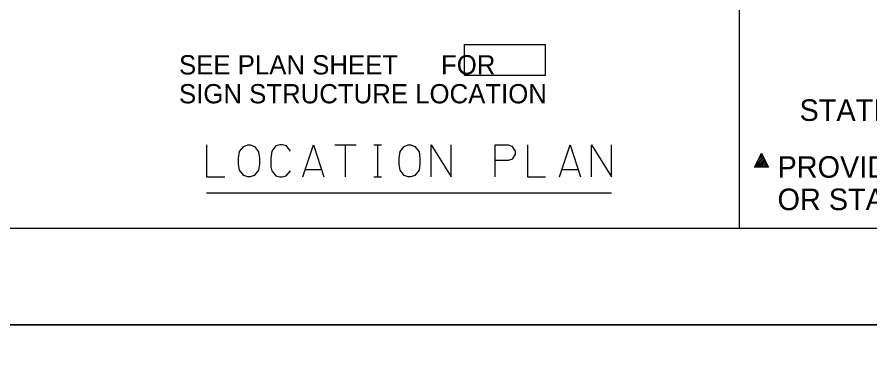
# Model space of a CAD drawing. Extents: x 3831399 to 3833095, y 499014 to 500202.
# Drawn here: x 3832621.3 to 3832754.1, y 499600.5 to 499655.9 of the extents above; entities that cross this region are included whole.
import ezdxf

# ---------------------------------------------------------------- set-up
doc = ezdxf.new("R2010")
doc.units = 0
for name, color, linetype in [('2', 7, 'Continuous'), ('DIM TXT', 7, 'Continuous'), ('Level 10', 7, 'Continuous'), ('Level 2', 7, 'Continuous'), ('PLT-BNDY', 7, 'Continuous')]:
    doc.layers.add(name, color=color, linetype=linetype)

msp = doc.modelspace()

# ---------------------------------------------------------------- linework, layer by layer
at = {"layer": '2'}
msp.add_line((3833066.16, 499623.03), (3832280.16, 499623.03), dxfattribs=at)
at = {"layer": 'DIM TXT'}
for p, q in [((3832733.69, 499724.78), (3832733.69, 499623.03)), ((3832736.14, 499632.58), (3832737.57, 499634.01)), ((3832736.35, 499633.05), (3832737.48, 499634.18)), ((3832736.4, 499632.58), (3832737.66, 499633.83)), ((3832736.61, 499633.58), (3832737.39, 499634.36)), ((3832736.67, 499632.58), (3832737.74, 499633.65)), ((3832736.88, 499634.11), (3832737.3, 499634.54)), ((3832737.14, 499634.64), (3832737.21, 499634.71)), ((3832736.94, 499632.58), (3832737.83, 499633.47)), ((3832737.2, 499632.58), (3832737.92, 499633.3)), ((3832737.47, 499632.58), (3832738.01, 499633.12)), ((3832737.73, 499632.58), (3832738.1, 499632.94)), ((3832738, 499632.58), (3832738.19, 499632.77)), ((3832738.26, 499632.58), (3832738.28, 499632.59)), ((3832859.35, 499623.03), (3832733.69, 499623.03))]:
    msp.add_line(p, q, dxfattribs=at)
msp.add_lwpolyline([(3832736.11, 499632.58), (3832737.2, 499634.75), (3832738.28, 499632.58)], close=True, dxfattribs=at)
at = {"layer": 'Level 10'}
for p, q in [((3832670.76, 499636.04), (3832674.06, 499636.04)), ((3832672.41, 499631.04), (3832672.41, 499636.04)), ((3832672.41, 499631.04), (3832672.41, 499636.04)), ((3832676.85, 499636.04), (3832678.03, 499636.04)), ((3832677.44, 499631.04), (3832677.44, 499636.04)), ((3832666.15, 499632.22), (3832668.63, 499632.22)), ((3832676.85, 499631.04), (3832678.03, 499631.04)), ((3832706.12, 499632.22), (3832708.6, 499632.22)), ((3832650.78, 499628.54), (3832713.83, 499628.54))]:
    msp.add_line(p, q, dxfattribs=at)
for points in [[(3832650.77, 499636.04), (3832650.77, 499631.04), (3832653.61, 499631.04)], [(3832657.19, 499636.04), (3832657.58, 499636.04), (3832658.25, 499635.76), (3832658.88, 499634.94), (3832659.03, 499633.96), (3832659.03, 499633.05), (3832658.88, 499632.07), (3832658.21, 499631.24), (3832657.58, 499631.04), (3832657.19, 499631.04), (3832656.6, 499631.24), (3832655.93, 499632.07), (3832655.77, 499633.05), (3832655.77, 499633.96), (3832655.93, 499634.98), (3832656.6, 499635.8), (3832657.19, 499636.04)], [(3832663.87, 499635.06), (3832663.24, 499635.88), (3832662.61, 499636.04), (3832662.18, 499636.04), (3832661.59, 499635.88), (3832660.92, 499635.06), (3832660.77, 499633.96), (3832660.77, 499633.37), (3832660.77, 499632.97), (3832660.8, 499632.62), (3832660.92, 499631.99), (3832661.59, 499631.2), (3832662.18, 499631.04), (3832662.54, 499631.04), (3832663.2, 499631.2), (3832663.87, 499631.99)], [(3832665.76, 499631.04), (3832667.41, 499636.04), (3832669.03, 499631.04)], [(3832682.16, 499636.04), (3832682.56, 499636.04), (3832683.23, 499635.76), (3832683.86, 499634.94), (3832684.01, 499633.96), (3832684.01, 499633.05), (3832683.86, 499632.07), (3832683.19, 499631.24), (3832682.56, 499631.04), (3832682.16, 499631.04), (3832681.57, 499631.24), (3832680.91, 499632.07), (3832680.75, 499633.05), (3832680.75, 499633.96), (3832680.91, 499634.98), (3832681.57, 499635.8), (3832682.16, 499636.04)], [(3832685.74, 499631.04), (3832685.74, 499636.04), (3832688.85, 499631.04), (3832688.85, 499636.04)], [(3832695.74, 499631.04), (3832695.74, 499636.04), (3832697.74, 499636.04), (3832698.33, 499635.84), (3832698.84, 499635.06), (3832698.84, 499634.58), (3832698.37, 499633.8), (3832697.74, 499633.6), (3832695.74, 499633.6)], [(3832700.73, 499636.04), (3832700.73, 499631.04), (3832703.56, 499631.04)], [(3832705.73, 499631.04), (3832707.38, 499636.04), (3832708.99, 499631.04)], [(3832710.72, 499631.04), (3832710.72, 499636.04), (3832713.83, 499631.04), (3832713.83, 499636.04)]]:
    msp.add_lwpolyline(points, dxfattribs=at)
at = {"layer": 'Level 2'}
for p, q in [((3832690.94, 499651.64), (3832703.52, 499651.64)), ((3832690.94, 499646.81), (3832690.94, 499651.64)), ((3832703.52, 499651.64), (3832703.52, 499646.81)), ((3832703.52, 499646.81), (3832690.94, 499646.81))]:
    msp.add_line(p, q, dxfattribs=at)
at = {"layer": 'PLT-BNDY'}
for points in [[(3832240.16, 500202.03), (3833081.16, 500202.03), (3833081.16, 499608.03), (3832240.16, 499608.03)], [(3832240.16, 499608.03), (3833081.16, 499608.03), (3833081.16, 499014.03), (3832240.16, 499014.03)]]:
    msp.add_lwpolyline(points, close=True, dxfattribs=at)

# ---------------------------------------------------------------- texts
at = {"layer": 'DIM TXT'}
for s, height, p in [('STATION', 3.359, (3832743.11, 499639.76)), ('PROVIDE EITHER LATITUDE/LONGITUDE', 3.3588, (3832739.68, 499630.91)), ('OR STATION AND OFFSET.', 3.3588, (3832739.68, 499625.87))]:
    msp.add_text(s, height=height, dxfattribs=at).set_placement(p)
at = {"layer": 'Level 10'}
for s, p in [('SEE PLAN SHEET      FOR', (3832646.49, 499646.99)), ('SIGN STRUCTURE LOCATION', (3832646.49, 499642.49))]:
    msp.add_text(s, height=2.9999, dxfattribs=at).set_placement(p)

doc.saveas('drawing.dxf')
